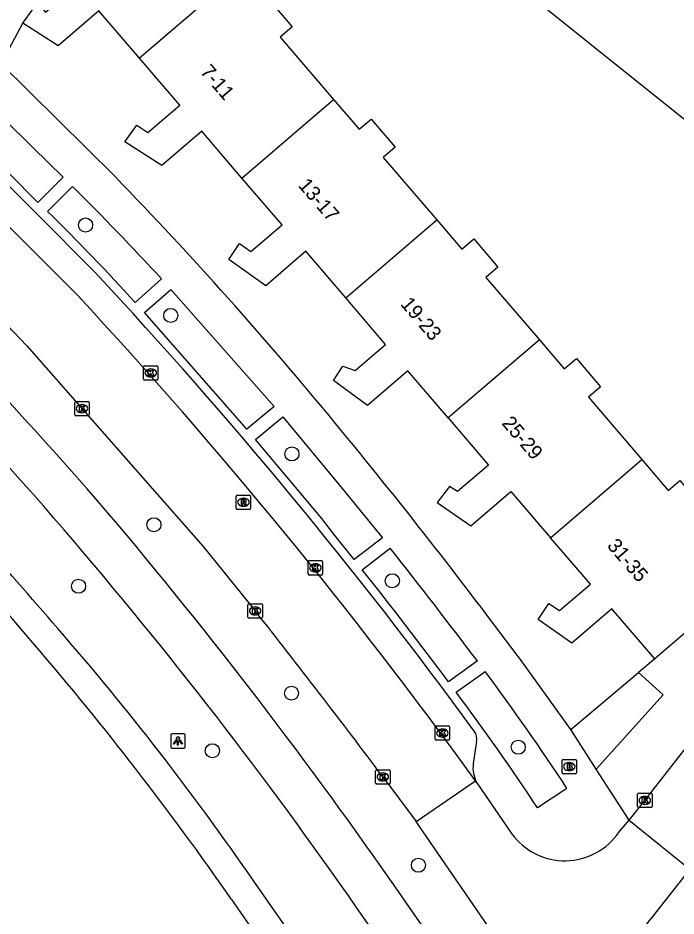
# Model space of a CAD drawing. Extents: x 159888 to 160757, y 384031 to 384746.
# Drawn here: x 160216.5 to 160262.2, y 384346.6 to 384409 of the extents above; entities that cross this region are included whole.
import ezdxf

# ---------------------------------------------------------------- set-up
doc = ezdxf.new("R2010")
doc.units = 0
for name, color, linetype in [('IMGEO_Boom', 7, 'Continuous'), ('IMGEO_Brandkraan', 7, 'Continuous'), ('IMGEO_Fietspad_gesloten', 7, 'Continuous'), ('IMGEO_Groenvoorziening', 7, 'Continuous'), ('IMGEO_Kolk', 7, 'Continuous'), ('IMGEO_Lichtpunt', 7, 'Continuous'), ('IMGEO_Pand', 7, 'Continuous'), ('IMGEO_Pand_nummerreeks', 7, 'Continuous'), ('IMGEO_Rijbaan_lokaal_open', 7, 'Continuous'), ('IMGEO_Rioolput', 7, 'Continuous'), ('IMGEO_Voetpad_halfverhard', 7, 'Continuous'), ('IMGEO_Voetpad_open', 7, 'Continuous')]:
    doc.layers.add(name, color=color, linetype=linetype)

msp = doc.modelspace()

# ---------------------------------------------------------------- linework, layer by layer
at = {"layer": 'IMGEO_Boom'}
for centre in [(160221.176, 384394.632), (160227.097, 384388.351), (160235.515, 384378.728), (160225.925, 384373.811), (160242.492, 384369.915), (160220.692, 384369.533), (160235.489, 384362.106), (160251.245, 384358.351), (160229.99, 384358.108), (160244.306, 384350.152)]:
    msp.add_circle(centre, 0.489, dxfattribs=at)
at = {"layer": 'IMGEO_Brandkraan'}
for p, q in [((160254.288, 384356.578), (160254.288, 384357.43)), ((160254.363, 384357.504), (160255.215, 384357.504)), ((160254.776, 384357.284), (160254.801, 384357.284)), ((160255.289, 384357.43), (160255.289, 384356.578)), ((160255.215, 384356.504), (160254.363, 384356.504)), ((160254.799, 384356.724), (160254.774, 384356.724))]:
    msp.add_line(p, q, dxfattribs=at)
for points in [[(160254.288, 384356.578), (160254.288, 384357.43)], [(160254.363, 384357.504), (160255.215, 384357.504)], [(160254.636, 384357.204), (160254.636, 384356.804), (160254.849, 384356.804)], [(160254.867, 384357.204), (160254.636, 384357.204)], [(160254.815, 384357.123), (160254.761, 384357.123), (160254.761, 384357.047)], [(160254.761, 384357.047), (160254.814, 384357.047)], [(160254.823, 384356.971), (160254.761, 384356.971), (160254.761, 384356.89)], [(160255.289, 384357.43), (160255.289, 384356.578)], [(160255.215, 384356.504), (160254.363, 384356.504)], [(160254.761, 384356.89), (160254.823, 384356.89)]]:
    msp.add_lwpolyline(points, dxfattribs=at)
for centre, radius, start, end in [((160254.365, 384357.428), 0.0765, 91.55205, 178.44795), ((160254.365, 384357.428), 0.0765, 91.55205, 178.44795), ((160254.816, 384357.085), 0.0379, 267.82845, 90.93552), ((160254.824, 384356.93), 0.0404, 269.87594, 90.50774), ((160254.871, 384357.059), 0.145, 59.4692, 91.53667), ((160254.896, 384357.106), 0.0922, 285.51372, 58.15012), ((160254.901, 384356.914), 0.105, 301.31148, 78.98903), ((160255.213, 384357.428), 0.0765, 1.55205, 88.44795), ((160255.213, 384357.428), 0.0765, 1.55205, 88.44795), ((160254.365, 384356.58), 0.0765, 181.55205, 268.44795), ((160254.365, 384356.58), 0.0765, 181.55205, 268.44795), ((160254.855, 384357.055), 0.251, 268.66757, 293.53466), ((160255.213, 384356.58), 0.0765, 271.55205, 358.44795), ((160255.213, 384356.58), 0.0765, 271.55205, 358.44795)]:
    msp.add_arc(centre, radius, start, end, dxfattribs=at)
for centre, major_axis, ratio, start_param, end_param in [((160254.775, 384357.004), (-0.387, 0.002), 0.722429, 4.712389, 7.853982), ((160254.8, 384357.004), (-0.39, 0.002), 0.717154, 1.570796, 4.712389)]:
    msp.add_ellipse(centre, major_axis=major_axis, ratio=ratio, start_param=start_param, end_param=end_param, dxfattribs=at)
at = {"layer": 'IMGEO_Fietspad_gesloten'}
msp.add_lwpolyline([(160246.571, 384343.077), (160243.679, 384347.225)], dxfattribs=at)
for centre, radius, start, end in [((160012.381, 384193.747), 277.425, 40.47548, 47.64714), ((160025.251, 384206.756), 256.111, 40.11751, 47.91695), ((159956.836, 384149.758), 348.241, 34.54418, 40.04879), ((159976.212, 384163.804), 321.292, 34.44172, 40.34)]:
    msp.add_arc(centre, radius, start, end, dxfattribs=at)
at = {"layer": 'IMGEO_Groenvoorziening'}
msp.add_lwpolyline([(160254.889, 384359.573), (160259.602, 384363.534)], dxfattribs=at)
at = {"layer": 'IMGEO_Kolk'}
for p, q in [((160225.208, 384383.93), (160225.208, 384384.782)), ((160225.283, 384384.856), (160226.135, 384384.856)), ((160225.696, 384384.636), (160225.721, 384384.636)), ((160226.209, 384384.782), (160226.209, 384383.93)), ((160226.135, 384383.856), (160225.283, 384383.856)), ((160225.719, 384384.076), (160225.694, 384384.076)), ((160220.429, 384381.453), (160220.429, 384382.305)), ((160220.504, 384382.379), (160221.356, 384382.379)), ((160220.917, 384382.159), (160220.942, 384382.159)), ((160221.43, 384382.305), (160221.43, 384381.453)), ((160221.356, 384381.379), (160220.504, 384381.379)), ((160220.94, 384381.599), (160220.915, 384381.599)), ((160236.724, 384371.314), (160237.576, 384371.314)), ((160236.649, 384370.388), (160236.649, 384371.24)), ((160237.137, 384371.094), (160237.162, 384371.094)), ((160237.65, 384371.24), (160237.65, 384370.388)), ((160237.576, 384370.314), (160236.724, 384370.314)), ((160237.16, 384370.534), (160237.135, 384370.534)), ((160232.464, 384367.395), (160232.464, 384368.247)), ((160232.539, 384368.321), (160233.391, 384368.321)), ((160233.465, 384368.247), (160233.465, 384367.395)), ((160232.975, 384367.541), (160232.95, 384367.541)), ((160232.952, 384368.101), (160232.977, 384368.101)), ((160233.391, 384367.321), (160232.539, 384367.321)), ((160245.472, 384358.908), (160245.472, 384359.76)), ((160245.547, 384359.834), (160246.399, 384359.834)), ((160245.96, 384359.614), (160245.985, 384359.614)), ((160246.473, 384359.76), (160246.473, 384358.908)), ((160246.399, 384358.834), (160245.547, 384358.834)), ((160245.983, 384359.054), (160245.958, 384359.054)), ((160241.336, 384355.862), (160241.336, 384356.714)), ((160241.411, 384356.788), (160242.263, 384356.788)), ((160241.824, 384356.568), (160241.849, 384356.568)), ((160242.337, 384356.714), (160242.337, 384355.862)), ((160242.263, 384355.788), (160241.411, 384355.788)), ((160241.847, 384356.008), (160241.822, 384356.008)), ((160259.539, 384354.231), (160259.539, 384355.083)), ((160259.614, 384355.157), (160260.466, 384355.157)), ((160260.54, 384355.083), (160260.54, 384354.231)), ((160260.027, 384354.937), (160260.052, 384354.937)), ((160260.466, 384354.157), (160259.614, 384354.157)), ((160260.05, 384354.377), (160260.025, 384354.377))]:
    msp.add_line(p, q, dxfattribs=at)
for points in [[(160225.208, 384383.93), (160225.208, 384384.782)], [(160225.283, 384384.856), (160226.135, 384384.856)], [(160225.529, 384384.556), (160225.652, 384384.556), (160225.652, 384384.405), (160225.782, 384384.556), (160225.946, 384384.556), (160225.8, 384384.405), (160225.953, 384384.156), (160225.801, 384384.156), (160225.716, 384384.32), (160225.652, 384384.253), (160225.652, 384384.156), (160225.529, 384384.156), (160225.529, 384384.556)], [(160226.209, 384384.782), (160226.209, 384383.93)], [(160226.135, 384383.856), (160225.283, 384383.856)], [(160220.429, 384381.453), (160220.429, 384382.305)], [(160220.504, 384382.379), (160221.356, 384382.379)], [(160220.75, 384382.079), (160220.873, 384382.079), (160220.873, 384381.928), (160221.003, 384382.079), (160221.167, 384382.079), (160221.021, 384381.928), (160221.174, 384381.679), (160221.022, 384381.679), (160220.937, 384381.843), (160220.873, 384381.776), (160220.873, 384381.679), (160220.75, 384381.679), (160220.75, 384382.079)], [(160221.43, 384382.305), (160221.43, 384381.453)], [(160221.356, 384381.379), (160220.504, 384381.379)], [(160236.724, 384371.314), (160237.576, 384371.314)], [(160236.649, 384370.388), (160236.649, 384371.24)], [(160236.97, 384371.014), (160237.093, 384371.014), (160237.093, 384370.863), (160237.223, 384371.014), (160237.387, 384371.014), (160237.241, 384370.863), (160237.394, 384370.614), (160237.242, 384370.614), (160237.157, 384370.778), (160237.093, 384370.711), (160237.093, 384370.614), (160236.97, 384370.614), (160236.97, 384371.014)], [(160237.65, 384371.24), (160237.65, 384370.388)], [(160237.576, 384370.314), (160236.724, 384370.314)], [(160232.464, 384367.395), (160232.464, 384368.247)], [(160232.539, 384368.321), (160233.391, 384368.321)], [(160233.465, 384368.247), (160233.465, 384367.395)], [(160232.785, 384368.021), (160232.908, 384368.021), (160232.908, 384367.87), (160233.038, 384368.021), (160233.202, 384368.021), (160233.056, 384367.87), (160233.209, 384367.621), (160233.057, 384367.621), (160232.972, 384367.785), (160232.908, 384367.718), (160232.908, 384367.621), (160232.785, 384367.621), (160232.785, 384368.021)], [(160233.391, 384367.321), (160232.539, 384367.321)], [(160245.472, 384358.908), (160245.472, 384359.76)], [(160245.547, 384359.834), (160246.399, 384359.834)], [(160245.793, 384359.534), (160245.916, 384359.534), (160245.916, 384359.383), (160246.046, 384359.534), (160246.21, 384359.534), (160246.064, 384359.383), (160246.217, 384359.134), (160246.065, 384359.134), (160245.98, 384359.298), (160245.916, 384359.231), (160245.916, 384359.134), (160245.793, 384359.134), (160245.793, 384359.534)], [(160246.473, 384359.76), (160246.473, 384358.908)], [(160246.399, 384358.834), (160245.547, 384358.834)], [(160241.336, 384355.862), (160241.336, 384356.714)], [(160241.411, 384356.788), (160242.263, 384356.788)], [(160241.657, 384356.488), (160241.78, 384356.488), (160241.78, 384356.337), (160241.91, 384356.488), (160242.074, 384356.488), (160241.928, 384356.337), (160242.081, 384356.088), (160241.929, 384356.088), (160241.844, 384356.252), (160241.78, 384356.185), (160241.78, 384356.088), (160241.657, 384356.088), (160241.657, 384356.488)], [(160242.337, 384356.714), (160242.337, 384355.862)], [(160242.263, 384355.788), (160241.411, 384355.788)], [(160259.539, 384354.231), (160259.539, 384355.083)], [(160259.614, 384355.157), (160260.466, 384355.157)], [(160260.54, 384355.083), (160260.54, 384354.231)], [(160259.86, 384354.857), (160259.983, 384354.857), (160259.983, 384354.706), (160260.113, 384354.857), (160260.277, 384354.857), (160260.131, 384354.706), (160260.284, 384354.457), (160260.132, 384354.457), (160260.047, 384354.621), (160259.983, 384354.554), (160259.983, 384354.457), (160259.86, 384354.457), (160259.86, 384354.857)], [(160260.466, 384354.157), (160259.614, 384354.157)]]:
    msp.add_lwpolyline(points, dxfattribs=at)
for centre, start, end in [((160225.285, 384384.78), 91.55205, 178.44795), ((160225.285, 384384.78), 91.55205, 178.44795), ((160226.133, 384384.78), 1.55205, 88.44795), ((160226.133, 384384.78), 1.55205, 88.44795), ((160225.285, 384383.932), 181.55205, 268.44795), ((160225.285, 384383.932), 181.55205, 268.44795), ((160226.133, 384383.932), 271.55205, 358.44795), ((160226.133, 384383.932), 271.55205, 358.44795), ((160220.506, 384382.303), 91.55205, 178.44795), ((160220.506, 384382.303), 91.55205, 178.44795), ((160221.354, 384382.303), 1.55205, 88.44795), ((160221.354, 384382.303), 1.55205, 88.44795), ((160220.506, 384381.455), 181.55205, 268.44795), ((160220.506, 384381.455), 181.55205, 268.44795), ((160221.354, 384381.455), 271.55205, 358.44795), ((160221.354, 384381.455), 271.55205, 358.44795), ((160236.726, 384371.238), 91.55205, 178.44795), ((160236.726, 384371.238), 91.55205, 178.44795), ((160237.574, 384371.238), 1.55205, 88.44795), ((160237.574, 384371.238), 1.55205, 88.44795), ((160236.726, 384370.39), 181.55205, 268.44795), ((160236.726, 384370.39), 181.55205, 268.44795), ((160237.574, 384370.39), 271.55205, 358.44795), ((160237.574, 384370.39), 271.55205, 358.44795), ((160232.541, 384368.245), 91.55205, 178.44795), ((160232.541, 384368.245), 91.55205, 178.44795), ((160233.389, 384368.245), 1.55205, 88.44795), ((160233.389, 384368.245), 1.55205, 88.44795), ((160232.541, 384367.397), 181.55205, 268.44795), ((160232.541, 384367.397), 181.55205, 268.44795), ((160233.389, 384367.397), 271.55205, 358.44795), ((160233.389, 384367.397), 271.55205, 358.44795), ((160245.549, 384359.758), 91.55205, 178.44795), ((160245.549, 384359.758), 91.55205, 178.44795), ((160246.397, 384359.758), 1.55205, 88.44795), ((160246.397, 384359.758), 1.55205, 88.44795), ((160245.549, 384358.91), 181.55205, 268.44795), ((160245.549, 384358.91), 181.55205, 268.44795), ((160246.397, 384358.91), 271.55205, 358.44795), ((160246.397, 384358.91), 271.55205, 358.44795), ((160241.413, 384356.712), 91.55205, 178.44795), ((160241.413, 384356.712), 91.55205, 178.44795), ((160242.261, 384356.712), 1.55205, 88.44795), ((160242.261, 384356.712), 1.55205, 88.44795), ((160241.413, 384355.864), 181.55205, 268.44795), ((160241.413, 384355.864), 181.55205, 268.44795), ((160242.261, 384355.864), 271.55205, 358.44795), ((160242.261, 384355.864), 271.55205, 358.44795), ((160259.616, 384355.081), 91.55205, 178.44795), ((160259.616, 384355.081), 91.55205, 178.44795), ((160260.464, 384355.081), 1.55205, 88.44795), ((160260.464, 384355.081), 1.55205, 88.44795), ((160259.616, 384354.233), 181.55205, 268.44795), ((160259.616, 384354.233), 181.55205, 268.44795), ((160260.464, 384354.233), 271.55205, 358.44795), ((160260.464, 384354.233), 271.55205, 358.44795)]:
    msp.add_arc(centre, 0.0765, start, end, dxfattribs=at)
for centre, major_axis, ratio, start_param, end_param in [((160225.695, 384384.356), (-0.387, 0.002), 0.722429, 4.712389, 7.853982), ((160225.72, 384384.356), (-0.39, 0.002), 0.717154, 1.570796, 4.712389), ((160220.916, 384381.879), (-0.387, 0.002), 0.722429, 4.712389, 7.853982), ((160220.941, 384381.879), (-0.39, 0.002), 0.717154, 1.570796, 4.712389), ((160237.136, 384370.814), (-0.387, 0.002), 0.722429, 4.712389, 7.853982), ((160237.161, 384370.814), (-0.39, 0.002), 0.717154, 1.570796, 4.712389), ((160232.951, 384367.821), (-0.387, 0.002), 0.722429, 4.712389, 7.853982), ((160232.976, 384367.821), (-0.39, 0.002), 0.717154, 1.570796, 4.712389), ((160245.959, 384359.334), (-0.387, 0.002), 0.722429, 4.712389, 7.853982), ((160245.984, 384359.334), (-0.39, 0.002), 0.717154, 1.570796, 4.712389), ((160241.823, 384356.288), (-0.387, 0.002), 0.722429, 4.712389, 7.853982), ((160241.848, 384356.288), (-0.39, 0.002), 0.717154, 1.570796, 4.712389), ((160260.026, 384354.657), (-0.387, 0.002), 0.722429, 4.712389, 7.853982), ((160260.051, 384354.657), (-0.39, 0.002), 0.717154, 1.570796, 4.712389)]:
    msp.add_ellipse(centre, major_axis=major_axis, ratio=ratio, start_param=start_param, end_param=end_param, dxfattribs=at)
at = {"layer": 'IMGEO_Lichtpunt'}
for p, q in [((160227.097, 384359.19), (160227.097, 384358.383)), ((160227.097, 384359.19), (160227.097, 384358.383)), ((160227.999, 384359.285), (160227.191, 384359.285)), ((160227.999, 384359.285), (160227.191, 384359.285)), ((160228.093, 384358.383), (160228.093, 384359.19)), ((160228.093, 384358.383), (160228.093, 384359.19)), ((160227.191, 384358.289), (160227.999, 384358.289)), ((160227.191, 384358.289), (160227.999, 384358.289))]:
    msp.add_line(p, q, dxfattribs=at)
for points in [[(160227.471, 384358.854), (160227.51, 384358.826), (160227.322, 384358.564), (160227.284, 384358.591), (160227.471, 384358.854)], [(160227.573, 384358.806), (160227.62, 384358.806), (160227.62, 384358.484), (160227.573, 384358.484), (160227.573, 384358.806)], [(160227.683, 384358.826), (160227.721, 384358.853), (160227.908, 384358.591), (160227.869, 384358.563), (160227.683, 384358.826)]]:
    msp.add_lwpolyline(points, dxfattribs=at)
msp.add_circle((160227.596, 384358.988), 0.0994, dxfattribs=at)
for centre, start, end in [((160227.191, 384359.19), 90, 180), ((160227.191, 384359.19), 90, 180), ((160227.999, 384359.19), 0, 90), ((160227.999, 384359.19), 0, 90), ((160227.191, 384358.383), 180, 270), ((160227.191, 384358.383), 180, 270), ((160227.999, 384358.383), 270, 0), ((160227.999, 384358.383), 270, 360)]:
    msp.add_arc(centre, 0.0946, start, end, dxfattribs=at)
at = {"layer": 'IMGEO_Pand'}
for points in [[(160284.068, 384427.196), (160263.423, 384401.459), (160241.705, 384418.881)], [(160216.817, 384408.667), (160217.838, 384410.06), (160218.384, 384409.423), (160220.568, 384411.293), (160217.651, 384414.7)], [(160231.281, 384411.679), (160224.921, 384406.231)], [(160231.281, 384411.679), (160233.024, 384409.644), (160233.86, 384410.36), (160235.539, 384408.4), (160234.703, 384407.684), (160238.416, 384403.347)], [(160224.921, 384406.231), (160222.112, 384409.511), (160219.269, 384407.076), (160216.817, 384408.667)], [(160232.048, 384397.893), (160229.261, 384401.148), (160226.47, 384398.758), (160223.915, 384400.407), (160224.746, 384401.572), (160225.516, 384401.057), (160227.729, 384402.952), (160224.921, 384406.231)], [(160232.048, 384397.893), (160238.416, 384403.347)], [(160238.416, 384403.347), (160240.185, 384401.282), (160241.021, 384401.998), (160242.7, 384400.038), (160241.863, 384399.321), (160245.577, 384394.985)], [(160239.258, 384389.573), (160236.489, 384392.807), (160233.695, 384390.414), (160231.142, 384392.248), (160231.874, 384393.353), (160232.674, 384392.788), (160234.835, 384394.639), (160232.048, 384397.893)], [(160239.258, 384389.573), (160245.577, 384394.985)], [(160245.577, 384394.985), (160247.317, 384392.955), (160248.153, 384393.671), (160249.832, 384391.711), (160248.995, 384390.994), (160252.709, 384386.658)], [(160246.369, 384381.228), (160243.569, 384384.497), (160240.766, 384382.096), (160238.402, 384383.829), (160239.065, 384384.832), (160239.915, 384384.532), (160242.027, 384386.34), (160239.258, 384389.573)], [(160252.709, 384386.658), (160246.369, 384381.228)], [(160252.709, 384386.658), (160254.444, 384384.632), (160255.28, 384385.348), (160256.959, 384383.388), (160256.122, 384382.671), (160259.836, 384378.335)], [(160246.369, 384381.228), (160249.168, 384377.959), (160247.014, 384376.12), (160246.472, 384376.455), (160245.621, 384375.35), (160247.942, 384373.738), (160250.734, 384376.129), (160253.495, 384372.905)], [(160253.495, 384372.905), (160259.836, 384378.335)], [(160259.836, 384378.335), (160261.666, 384376.198), (160262.477, 384376.892), (160264.162, 384374.923), (160266.223, 384376.687), (160267.744, 384374.911), (160264.872, 384372.453), (160267.058, 384369.901)], [(160260.735, 384364.486), (160257.748, 384367.974), (160254.967, 384365.592), (160252.638, 384367.22), (160253.369, 384368.345), (160254.116, 384367.849), (160256.256, 384369.681), (160253.495, 384372.905)], [(160267.058, 384369.901), (160260.735, 384364.486)]]:
    msp.add_lwpolyline(points, dxfattribs=at)
at = {"layer": 'IMGEO_Rijbaan_lokaal_open'}
for points in [[(160258.945, 384353.29), (160260.04, 384354.657), (160262.944, 384358.346), (160266.78, 384363.051), (160279.413, 384378.913), (160290.673, 384392.988), (160303.911, 384409.606), (160304.069, 384409.799), (160304.613, 384410.388), (160305.206, 384410.925), (160305.846, 384411.408), (160306.526, 384411.831), (160307.241, 384412.192), (160307.985, 384412.487), (160308.753, 384412.715), (160309.538, 384412.874), (160310.334, 384412.961), (160311.135, 384412.977), (160311.934, 384412.922)], [(160220.611, 384389.761), (160210.66, 384399.705), (160209.826, 384400.498)], [(160205.606, 384397.619), (160209.459, 384393.839), (160211.385, 384391.997), (160214.807, 384388.628), (160217.106, 384386.23), (160229.358, 384372.29), (160232.965, 384367.821)], [(160241.837, 384356.288), (160244.139, 384353.187)], [(160244.139, 384353.187), (160248.279, 384356.005)], [(160248.36, 384355.88), (160248.279, 384356.005)], [(160248.36, 384355.88), (160250.785, 384352.356)], [(160258.248, 384352.472), (160258.945, 384353.29)], [(160258.945, 384353.29), (160259.2, 384353.077), (160263.16, 384349.885)], [(160249.887, 384344.834), (160244.389, 384352.849), (160244.139, 384353.187)], [(160263.16, 384349.885), (160260.594, 384346.622)]]:
    msp.add_lwpolyline(points, dxfattribs=at)
for centre, radius, start, end in [((159959.248, 384147.319), 356.495, 35.83006, 42.84924), ((159842.131, 384057.985), 498.748, 36.73422, 38.40585), ((160254.476, 384355.01), 4.546, 215.71361, 326.06738), ((160265.449, 384342.389), 6.441, 138.91095, 210.88795)]:
    msp.add_arc(centre, radius, start, end, dxfattribs=at)
at = {"layer": 'IMGEO_Rioolput'}
for p, q in [((160231.647, 384374.943), (160231.647, 384375.795)), ((160231.722, 384375.869), (160232.574, 384375.869)), ((160232.648, 384375.795), (160232.648, 384374.943)), ((160232.158, 384375.089), (160232.133, 384375.089)), ((160232.135, 384375.649), (160232.16, 384375.649)), ((160232.574, 384374.869), (160231.722, 384374.869))]:
    msp.add_line(p, q, dxfattribs=at)
for points in [[(160231.647, 384374.943), (160231.647, 384375.795)], [(160231.722, 384375.869), (160232.574, 384375.869)], [(160232.648, 384375.795), (160232.648, 384374.943)], [(160232.236, 384375.567), (160231.984, 384375.569), (160231.984, 384375.169)], [(160231.984, 384375.169), (160232.108, 384375.169), (160232.108, 384375.331), (160232.119, 384375.331)], [(160232.162, 384375.488), (160232.108, 384375.488), (160232.108, 384375.407)], [(160232.108, 384375.407), (160232.16, 384375.407)], [(160232.166, 384375.302), (160232.237, 384375.169), (160232.377, 384375.169), (160232.312, 384375.295)], [(160232.574, 384374.869), (160231.722, 384374.869)]]:
    msp.add_lwpolyline(points, dxfattribs=at)
for centre, radius, start, end in [((160231.724, 384375.793), 0.0765, 91.55205, 178.44795), ((160231.724, 384375.793), 0.0765, 91.55205, 178.44795), ((160232.572, 384375.793), 0.0765, 1.55205, 88.44795), ((160232.572, 384375.793), 0.0765, 1.55205, 88.44795), ((160232.118, 384375.278), 0.0533, 26.02933, 88.69889), ((160232.144, 384375.596), 0.19, 274.7715, 282.96867), ((160232.168, 384375.392), 0.0964, 77.00612, 93.18647), ((160232.182, 384375.449), 0.0378, 276.66336, 79.67722), ((160232.235, 384375.457), 0.109, 350.36119, 89.41601), ((160232.233, 384375.457), 0.112, 277.58423, 350.98172), ((160232.217, 384375.242), 0.108, 29.51342, 73.79051), ((160231.724, 384374.945), 0.0765, 181.55205, 268.44795), ((160231.724, 384374.945), 0.0765, 181.55205, 268.44795), ((160232.572, 384374.945), 0.0765, 271.55205, 358.44795), ((160232.572, 384374.945), 0.0765, 271.55205, 358.44795)]:
    msp.add_arc(centre, radius, start, end, dxfattribs=at)
for centre, major_axis, ratio, start_param, end_param in [((160232.134, 384375.369), (-0.387, 0.002), 0.722429, 4.712389, 7.853982), ((160232.159, 384375.369), (-0.39, 0.002), 0.717154, 1.570796, 4.712389)]:
    msp.add_ellipse(centre, major_axis=major_axis, ratio=ratio, start_param=start_param, end_param=end_param, dxfattribs=at)
at = {"layer": 'IMGEO_Voetpad_halfverhard'}
for points in [[(160240.539, 384338.074), (160232.86, 384349.054)], [(160231.322, 384347.768), (160238.885, 384336.845)]]:
    msp.add_lwpolyline(points, dxfattribs=at)
for centre, radius, start, end in [((159980.908, 384163.386), 311.247, 40.47955, 47.64022), ((159961.589, 384145.635), 339.43, 40.61355, 42.06641), ((160072.088, 384238.361), 195.194, 34.54773, 41.06547), ((160053.624, 384224.453), 216.294, 34.75899, 40.67967)]:
    msp.add_arc(centre, radius, start, end, dxfattribs=at)
at = {"layer": 'IMGEO_Voetpad_open'}
for points in [[(160223.225, 384397.993), (160215.325, 384405.834), (160216.817, 384408.667)], [(160217.874, 384396.207), (160215.875, 384398.205), (160213.768, 384400.303), (160215.488, 384402.035), (160217.522, 384400.008), (160219.615, 384397.963), (160217.874, 384396.207)], [(160213.524, 384399.675), (160221.846, 384391.326)], [(160218.543, 384395.58), (160220.272, 384397.306)], [(160226.456, 384390.891), (160224.634, 384389.239)], [(160232.388, 384380.442), (160225.267, 384388.561), (160227.106, 384390.153), (160234.273, 384382.022), (160232.388, 384380.442)], [(160234.889, 384381.305), (160238.79, 384376.591), (160241.807, 384372.897), (160239.842, 384371.394), (160238.44, 384373.16), (160237.599, 384374.245), (160232.98, 384379.738), (160234.889, 384381.305)], [(160240.407, 384370.678), (160242.347, 384372.185)], [(160254.889, 384359.573), (160251.391, 384364.439)], [(160260.735, 384364.486), (160259.602, 384363.534)], [(160248.401, 384364.348), (160246.389, 384362.901)], [(160246.931, 384362.17), (160248.942, 384363.62)], [(160259.602, 384363.534), (160261.313, 384361.982), (160256.658, 384356.833)], [(160256.658, 384356.833), (160254.889, 384359.573)], [(160248.347, 384358.742), (160248.117, 384357.212)], [(160258.945, 384353.29), (160256.658, 384356.833)], [(160254.629, 384355.493), (160252.584, 384354.135)]]:
    msp.add_lwpolyline(points, dxfattribs=at)
for centre, radius, start, end in [((160022.988, 384203.662), 279.033, 39.41659, 44.14248), ((160077.49, 384253.478), 202.665, 42.68998, 45.20924), ((160110.822, 384286.01), 153.654, 42.20843, 45.48751), ((159969.953, 384156.223), 344.563, 36.14699, 43.0255), ((159928.033, 384124.513), 402.647, 36.57478, 39.53815), ((159783.253, 384011.283), 583.967, 37.199887, 38.17153), ((160022.386, 384196.789), 278.874, 36.55921, 38.57513), ((160101.502, 384254.393), 183.491, 33.43419, 36.53187), ((160112.542, 384261.615), 167.844, 33.45111, 36.80526), ((160247.478, 384358.933), 0.89, 347.62592, 36.84448), ((160250.288, 384356.92), 2.191, 172.3385, 208.33933)]:
    msp.add_arc(centre, radius, start, end, dxfattribs=at)

# ---------------------------------------------------------------- texts
at = {"layer": 'IMGEO_Pand_nummerreeks'}
for s, rotation, p in [('7-11', 310.59958, (160229.1, 384405.252)), ('13-17', 310.94908, (160235.897, 384397.356)), ('19-23', 310.45061, (160243.016, 384389.114)), ('25-29', 310.59958, (160250.048, 384380.833)), ('31-35', 310.82303, (160257.367, 384372.319))]:
    msp.add_text(s, height=1, rotation=rotation, dxfattribs=at).set_placement(p)

doc.saveas('drawing.dxf')
